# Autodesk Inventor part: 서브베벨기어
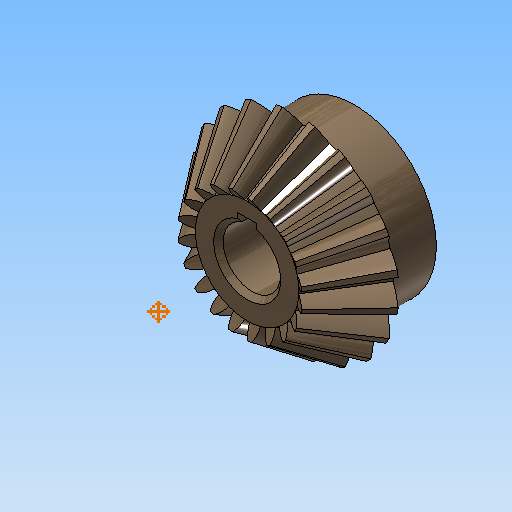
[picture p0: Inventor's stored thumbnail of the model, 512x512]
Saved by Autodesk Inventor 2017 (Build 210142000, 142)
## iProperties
Created: 2018-09
Part Number: 서브베벨기어
Material: 강철, 탄소
Document SubType Name: Modeling
Categories: <?xml version="1.0" encoding="UTF-16"?> <MemberInstance><Categories><FamilyTemplate><FamilyTemplateParameter ValueType="xs:double" Id="1" ObjectReferenceKey="da
Mass: 135.037 g
Surface Area: 63.6444 cm^2
Volume: 17.1585 cm^3
Density: 7.87 g/cm^3
Appearance: 얼룩무늬
CustomPartVersion: 1
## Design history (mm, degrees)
node "맨 위 점"
node "메쉬 평면2"
sketch "톱니 본체 스케치"
  geometry: L1 (0, 0)-(18.003, -31.331); L2 (18.003, -31.331)-(21.664, -28.891); L3 (21.664, -28.891)-(0, 0); L4 (20, -30)-(0, 0); L5 (10.813, -18.818)-(13.012, -17.352); L6 (18.003, -31.331)-(10.813, -18.818); L7 (21.664, -28.891)-(13.012, -17.352); L8 (0, -39.387)-(0, 6.564) reference; L9 (0, -30)-(21.664, -30)
  constraints: 16 end point, 4 point on line, 3 perpendicular, 2 collinear, 1 horizontal alignment, 1 vertical alignment
  dimensions: "d0" = 40 diameter of L4.start L8 (= da_de); "d1" = 36.00616 diameter of L1.end L8 (= da_dfe); "d2" = 43.3282 diameter of L2.end L8 (= da_dae); "d3" = 14.4 distance between parallel lines of L2 L5 (= da_b); "d4" = 28.8906 vertical distance of L2.end L1.start (= da_ve)
revolve "톱니 본체" sketch "톱니 본체 스케치" stored, may be unused: angle "d5" = 90 deg
node "시작점"
node "톱니 평면"
sketch "시작 스케치"
  geometry: L1 (0, -23.505)-(0, 10.645) reference; L2 (-0.834, -2.928)-(0.834, -2.928); A1 r 8.898 centre (-9.698, -3.713) between (-0.834, -2.928) and (-3.903, 3.04); A2 r 8.898 centre (9.698, -3.713) between (3.903, 3.04) and (0.834, -2.928); A3 r 27.357 centre (0, -24.037) between (3.903, 3.04) and (-3.903, 3.04); 1 further point
  constraints: 6 point on circle, 3 centre point, 3 symmetric about line, 2 end point, 1 coincident, 1 perpendicular, 1 other
  dimensions: "d7" = 8.89846 radius of A1 (= fd_rr); "d8" = 9.69794 horizontal distance of point (0, -24.037) A1.centre (= fd_x); "d9" = 20.32439 vertical distance of point (0, -24.037) A1.centre (= fd_y); "d57" = 27.35701 radius of A3 (= 0.5 x fd_dva + 0.3 x da_he); "d58" = 21.10901 distance from line of A3.centre L2 (= 0.5 x fd_dva - 1.12 x da_he)
node "끝점"
  node "끝 평면"
sketch "3D 스케치 오른쪽"
  node "Helical Curve Right" dims "d65" = 229.90621 (computed from da_dm, da_delta, da_beta), "d66" = 31.5, "d67" = 40 (= da_de), "d68" = -5.88003 (= -da_delta), "d69" = 12.16458 (computed from fd_loft, da_delta)
node "끝 평면 오른쪽"
sketch "끝 스케치 오른쪽"
  geometry: L1 (0, -22.649)-(0, 12.15) reference; L2 (-0.497, -1.72)-(0.497, -1.72); A1 r 5.299 centre (-5.775, -2.187) between (-0.497, -1.72) and (-2.324, 1.834); A2 r 5.299 centre (5.775, -2.187) between (2.324, 1.834) and (0.497, -1.72); A3 r 16.291 centre (0, -14.29) between (2.324, 1.834) and (-2.324, 1.834); 1 further point
  constraints: 6 point on circle, 3 centre point, 3 symmetric about line, 2 end point, 1 coincident, 1 perpendicular, 1 other
  dimensions: "d70" = 5.77526 horizontal distance of A3.centre A1.centre (computed from fd_x, fd_ratio); "d71" = 12.10346 vertical distance of point (0, -14.29) A1.centre (computed from fd_y, fd_ratio); "d72" = 5.29916 radius of A1 (computed from fd_rr, fd_ratio); "d73" = 12.57071 distance from line of point (0, -14.29) L2 (computed from d58, fd_ratio); "d74" = 16.29149 radius of A3 (computed from d57, fd_ratio)
feature "로프트 오른쪽" sketch "끝 스케치 오른쪽" dims "d75" = 0, "d77" = 0, "d79" = 0, "d80" = 90 deg, "d85" = 20, "d92" = 90 deg, "d93" = 90 deg, "da_teethtype" = 0 [user parameter]
sketch "3D 스케치 왼쪽"
  node "Helical Curve Left" dims "d26" = 229.90621 (computed from da_dm, da_delta, da_beta), "d27" = 12.16458 (computed from fd_loft, da_delta), "d28" = 40 (= da_de), "d29" = -5.88003 (= -da_delta)
node "끝 평면 왼쪽"
sketch "끝 스케치 왼쪽" dims "d56" = 10.82768 (derived)
  geometry: L1 (0, -35.087)-(0, 18.089) reference; L2 (-0.497, -1.716)-(0.497, -1.716); A1 r 5.299 centre (-5.775, -2.183) between (-0.497, -1.716) and (-2.324, 1.838); A2 r 5.299 centre (5.775, -2.183) between (2.324, 1.838) and (0.497, -1.716); A3 r 16.291 centre (0, -14.287) between (2.324, 1.838) and (-2.324, 1.838); 2 further points; 1 other entity
  constraints: 6 point on circle, 3 centre point, 3 symmetric about line, 2 end point, 1 coincident, 2 other
  dimensions: "d30" = 5.29916 radius of A1 (computed from fd_rr, fd_ratio); "d31" = 5.77526 horizontal distance of point (0, -14.287) A1.centre (computed from fd_x, fd_ratio); "d32" = 12.10346 vertical distance of A1.centre point (0, -14.287) (computed from fd_y, fd_ratio); "d61" = 16.29149 radius of A3 (computed from d57, fd_ratio); "d62" = 12.57071 distance from line of point (0, -14.287) L2 (computed from d58, fd_ratio)
feature "로프트 왼쪽" sketch "끝 스케치 왼쪽" dims "d35" = 0, "d37" = 0, "d39" = 0, "d40" = 90 deg, "d84" = 10, "d90" = 90 deg, "d91" = 90 deg, "da_teethtype" = 0 [user parameter]
sketch "본체 스케치"
  geometry: L1 (0, -35.038)-(0, -19.531) reference; L2 (18.003, -31.331)-(10.813, -18.818) reference; L3 (10.813, -18.818)-(0, -18.818); L4 (18.003, -31.331)-(0, -31.331)
  constraints: 4 end point, 2 perpendicular, 2 point on line
revolve "본체 고정" sketch "본체 스케치" stored, may be unused: angle "d46" = 90 deg
feature "피치 지름" dims angle "d47" = 90 deg
sketch "스케치8"
  geometry: C1 r 17 at (0, 0); 1 further point
  constraints: 1 centre point, 1 coincident
  dimensions: "d94" = 34 diameter of C1
extrude "돌출1" join sketch "스케치8" distance "d95" = 10; taper "d96" = 0 deg
sketch "스케치9"
  geometry: 1 further point
hole "구멍1" sketch "스케치9" at (0, 0) diameter "d97" = 12; stored, may be unused: countersink angle "d101" = 90 deg, drill point angle "d103" = 118 deg; dims "d98" = 6, "d99" = 4, "d100" = 2, "d102" = 8
sketch "스케치10"
  geometry: 1 further point
sketch "스케치11"
  geometry: 1 further point
sketch "스케치12"
  geometry: L1 (-2, 5.657)-(-2, 7.8); L2 (-2, 7.8)-(2, 7.8); L3 (2, 7.8)-(2, 5.657); A1 r 6 centre (0, 0) between (-2, 5.657) and (2, 5.657) reference; 1 further point
  constraints: 6 end point, 2 parallel, 2 point on circle, 1 perpendicular, 1 vertical
  dimensions: "d104" = 4 distance of L1.end L2.end; "d105" = 13.8 dimension on A1 L2
extrude "돌출2" cut sketch "스케치12" stored distance "d106" = 7; taper "d107" = 0 deg
chamfer "모따기1" distance "d108" = 1; stored, may be unused: second distance "d109" = 2, angle "d110" = 45 deg
body "Solid1"
feature "로프트" dims "d17" = 0, "d18" = 90 deg, "d19" = 0, "d20" = 90 deg, "d89" = 0, "da_teethtype" = 0 [user parameter]
pattern_circular "원형 패턴" dims angle "d22" = 360 deg, "d88" = 0, "da_teethtype" = 0 [user parameter]
pattern_circular "원형 패턴 오른쪽" dims angle "d82" = 360 deg, "da_teethtype" = 0 [user parameter]
pattern_circular "원형 패턴 왼쪽" dims angle "d42" = 360 deg, "da_teethtype" = 0 [user parameter]
sketch "끝 스케치"
  geometry: L1 (0, -15.359)-(0, 6.983) reference; L2 (-0.497, -1.72)-(0.497, -1.72); A1 r 5.299 centre (-5.775, -2.187) between (-0.497, -1.72) and (-2.324, 1.834); A2 r 5.299 centre (5.775, -2.187) between (2.324, 1.834) and (0.497, -1.72); A3 r 16.291 centre (0, -14.29) between (2.324, 1.834) and (-2.324, 1.834); 1 further point
  constraints: 6 point on circle, 3 centre point, 3 symmetric about line, 2 end point, 1 coincident, 1 other
  dimensions: "d12" = 5.29916 radius of A1 (computed from fd_rr, fd_ratio); "d15" = 5.77526 horizontal distance of A1.centre point (0, -14.29) (computed from fd_x, fd_ratio); "d16" = 12.10346 vertical distance of A1.centre point (0, -14.29) (computed from fd_y, fd_ratio); "d59" = 16.29149 radius of A3 (computed from d57, fd_ratio); "d60" = 12.57071 distance from line of A3.centre L2 (computed from d58, fd_ratio)
sketch "Sketch6"
  geometry: L1 (20, -30)-(0, 0) reference; L2 (0, -37.8)-(0, 6.3) reference
body "Srf1"
other parameters: "da_b" = 14.4 [user parameter; used in 2 equation terms], "da_de" = 40 [user parameter; used in 4 equation terms], "da_dae" = 43.3282 [user parameter; used in 2 equation terms], "da_dfe" = 36.00616 [user parameter; used in 1 equation term], "da_le" = 36.05551 [user parameter; used in 1 equation term], "da_omega" = 90 deg [user parameter; used in 1 equation term], "da_beta" = 0 [user parameter; used in 2 equation terms], "da_delta" = 5.88003 [user parameter; used in 8 equation terms], "da_alpha" = 20 deg [user parameter; used in 2 equation terms], "da_he" = 4.4 [user parameter; used in 4 equation terms], "da_ve" = 28.8906 [user parameter; used in 1 equation term], "fd_dv" = 48.07402 (computed from da_de, da_delta) [user parameter; used in 1 equation term], "fd_dva" = 52.07402 (computed from da_dae, da_delta) [user parameter; used in 3 equation terms], "fd_dvb" = 45.1748 (computed from fd_dv, da_alpha) [user parameter; used in 2 equation terms], "da_zv" = 240.37008 [user parameter; used in 1 equation term], "fd_loft" = 14.62 (= da_b + 0.05 x da_he) [user parameter; used in 4 equation terms], "fd_ratio" = 5.95514 (computed from da_le, fd_loft) [user parameter; used in 15 equation terms], "fd_rr" = 8.89846 (computed from fd_dd, fd_dvb) [user parameter; used in 6 equation terms], "fd_angle" = 0.66075 (computed from da_zv) [user parameter; used in 4 equation terms], "fd_x1" = 1.58709 (computed from da_dvw, fd_angle) [user parameter; used in 1 equation term], "fd_y1" = 23.98456 (computed from da_dvw, fd_angle) [user parameter; used in 1 equation term], "fd_x2" = 8.11084 (computed from fd_rr, fd_angle2, fd_angle) [user parameter; used in 1 equation term], "fd_y2" = 3.66016 (computed from fd_rr, fd_angle2, fd_angle) [user parameter; used in 1 equation term], "fd_x" = 9.69794 (= fd_x1 + fd_x2) [user parameter; used in 4 equation terms], "fd_y" = 20.32439 (= fd_y1 - fd_y2) [user parameter; used in 4 equation terms], "fd_angle2" = 3.57832 (computed from fd_dvb, fd_dd, da_alpha) [user parameter; used in 2 equation terms], "fd_dd" = 48.55402 (= fd_dva - 0.8 x da_he) [user parameter; used in 2 equation terms], "da_dvw" = 48.07402 [user parameter; used in 2 equation terms], "d11" = 14.62 (= fd_loft), "da_dm" = 32.01232 [user parameter; used in 2 equation terms], "da_x" = 0 [user parameter], "da_m" = 2 [user parameter], "d48" = 0, "d49" = 0, "d50" = 90 deg (= da_omega), "d51" = 9 deg (computed from da_z), "d52" = 0, "d53" = 0, "d54" = 0
